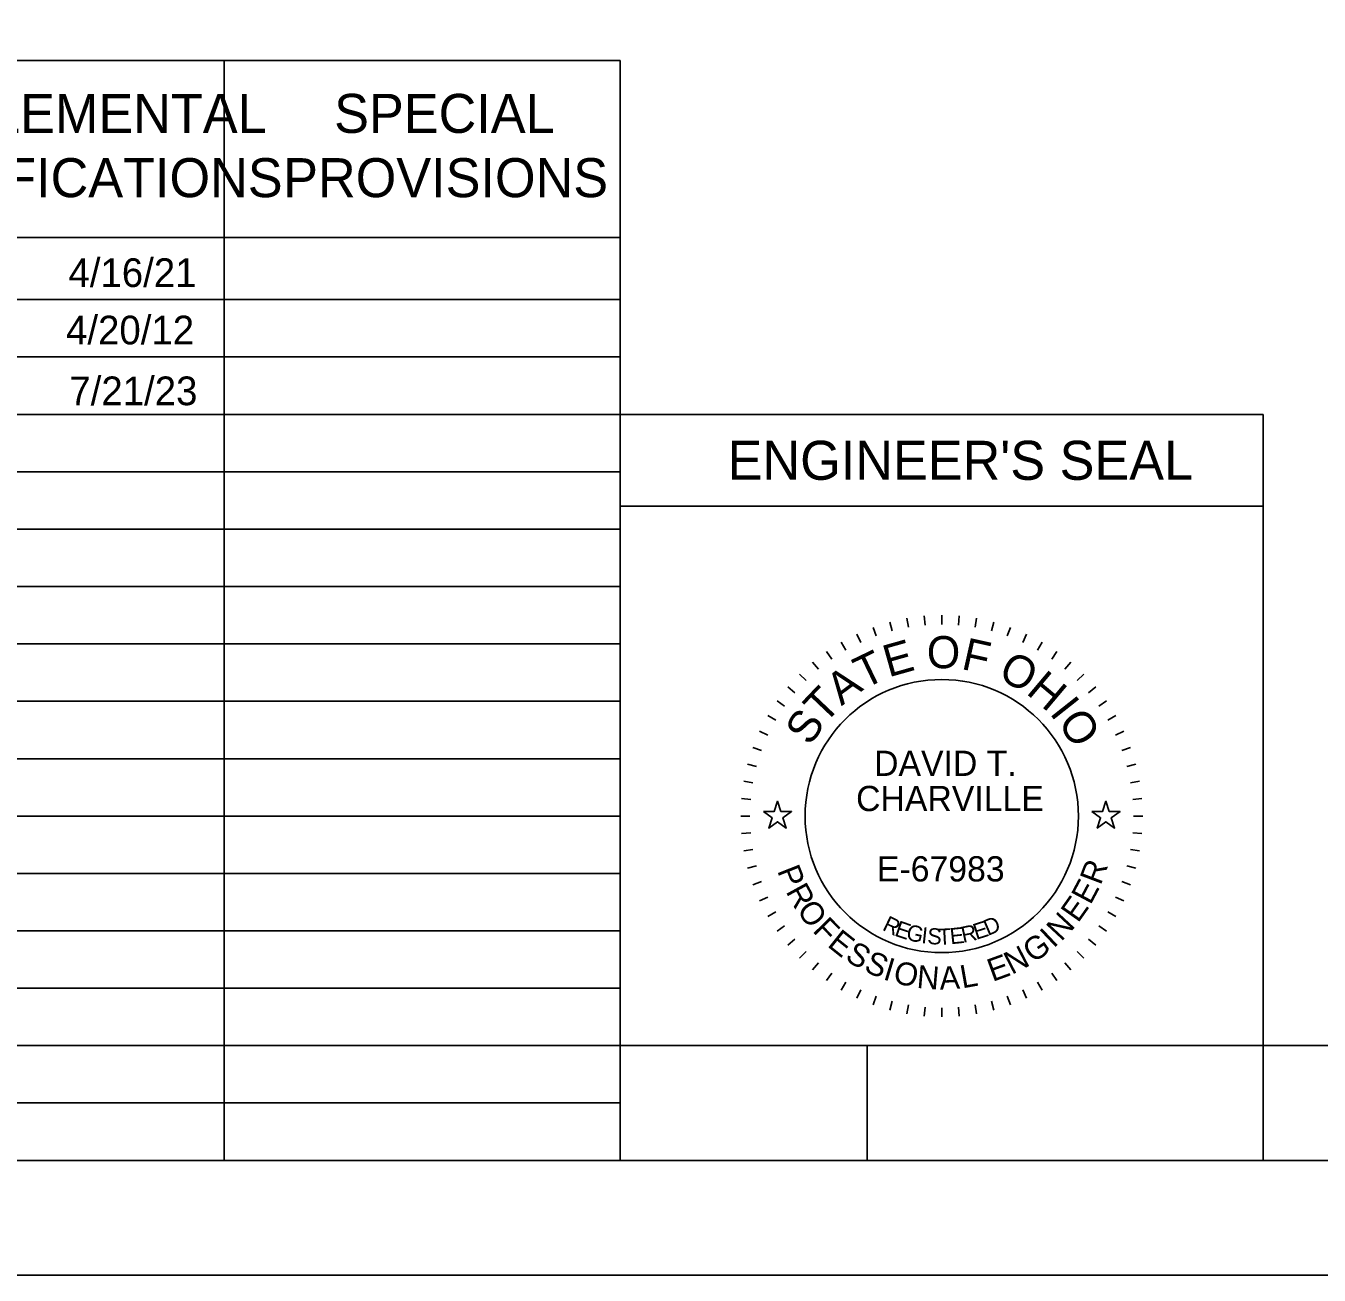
# Model space of a CAD drawing. Extents: x 0 to 40.2, y 0 to 22.
# Drawn here: x 22.74 to 28.37, y 0 to 5.44 of the extents above; entities that cross this region are included whole.
import ezdxf

# ---------------------------------------------------------------- set-up
doc = ezdxf.new("R2010")
doc.units = 0
for name, color, linetype in [('Default', 7, 'Continuous'), ('GM_X_Adjacent_County', 7, 'Continuous'), ('GM_X_Adjacent_County_Text', 7, 'Continuous'), ('GM_X_County', 7, 'Continuous'), ('GM_X_Township', 7, 'Continuous')]:
    doc.layers.add(name, color=color, linetype=linetype)

msp = doc.modelspace()

# ---------------------------------------------------------------- linework, layer by layer
at = {"layer": 'Default'}
for points in [[(25.9486, 2.02), (25.9955, 2.02), (26.01, 2.0645), (26.0245, 2.02), (26.0714, 2.02), (26.0335, 1.9924), (26.048, 1.9478), (26.01, 1.9754), (25.972, 1.9478), (25.9865, 1.9924)], [(27.3786, 2.02), (27.4255, 2.02), (27.44, 2.0645), (27.4545, 2.02), (27.5014, 2.02), (27.4635, 1.9924), (27.478, 1.9478), (27.44, 1.9754), (27.402, 1.9478), (27.4165, 1.9924)]]:
    msp.add_lwpolyline(points, close=True, dxfattribs=at)
at = {"layer": 'GM_X_Adjacent_County'}
for p, q in [((10.15, 5.2917), (23.6, 5.2917)), ((23.6, 0.5), (23.6, 5.2917)), ((23.6, 5.2917), (25.325, 5.2917)), ((25.325, 5.2917), (25.325, 0.5)), ((10.15, 4.5209), (23.6, 4.5209)), ((23.6, 4.5209), (25.325, 4.5209)), ((10.15, 4.25), (23.6, 4.25)), ((23.6, 4.25), (25.325, 4.25)), ((10.15, 4), (23.6, 4)), ((23.6, 4), (25.325, 4)), ((10.15, 3.75), (23.6, 3.75)), ((23.6, 0.5), (23.6, 3.75)), ((23.6, 3.75), (25.325, 3.75)), ((25.325, 0.5), (25.325, 3.75)), ((25.325, 3.75), (28.125, 3.75)), ((28.125, 3.75), (28.125, 0.5)), ((10.15, 3.5), (23.6, 3.5)), ((23.6, 3.5), (25.325, 3.5)), ((25.325, 3.35), (28.125, 3.35)), ((10.15, 3.25), (23.6, 3.25)), ((23.6, 3.25), (25.325, 3.25)), ((10.15, 3), (23.6, 3)), ((23.6, 3), (25.325, 3)), ((26.725, 2.875), (26.725, 2.835)), ((26.4257, 2.8222), (26.4394, 2.7846)), ((26.4985, 2.8452), (26.5089, 2.8065)), ((26.5731, 2.8617), (26.58, 2.8223)), ((26.6487, 2.8717), (26.6522, 2.8318)), ((26.8013, 2.8717), (26.7978, 2.8318)), ((26.8769, 2.8617), (26.87, 2.8223)), ((26.9515, 2.8452), (26.9411, 2.8065)), ((27.0243, 2.8222), (27.0106, 2.7846)), ((26.3552, 2.793), (26.3721, 2.7568)), ((27.0948, 2.793), (27.0779, 2.7568)), ((10.15, 2.75), (23.6, 2.75)), ((23.6, 2.75), (25.325, 2.75)), ((26.2231, 2.7168), (26.2461, 2.684)), ((26.2875, 2.7578), (26.3075, 2.7231)), ((27.1625, 2.7578), (27.1425, 2.7231)), ((27.2269, 2.7168), (27.2039, 2.684)), ((26.1626, 2.6703), (26.1883, 2.6396)), ((27.2874, 2.6703), (27.2617, 2.6396)), ((26.1063, 2.6187), (26.1346, 2.5904)), ((27.3437, 2.6187), (27.3154, 2.5904)), ((26.0547, 2.5624), (26.0854, 2.5367)), ((27.3953, 2.5624), (27.3646, 2.5367)), ((10.15, 2.5), (23.6, 2.5)), ((23.6, 2.5), (25.325, 2.5)), ((26.0082, 2.5019), (26.041, 2.4789)), ((27.4418, 2.5019), (27.409, 2.4789)), ((25.9672, 2.4375), (26.0019, 2.4175)), ((27.4828, 2.4375), (27.4481, 2.4175)), ((25.932, 2.3698), (25.9682, 2.3529)), ((27.518, 2.3698), (27.4818, 2.3529)), ((25.9028, 2.2993), (25.9404, 2.2856)), ((27.5472, 2.2993), (27.5096, 2.2856)), ((10.15, 2.25), (23.6, 2.25)), ((23.6, 2.25), (25.325, 2.25)), ((25.8798, 2.2265), (25.9185, 2.2161)), ((27.5702, 2.2265), (27.5315, 2.2161)), ((25.8633, 2.1519), (25.9027, 2.145)), ((27.5867, 2.1519), (27.5473, 2.145)), ((25.8533, 2.0763), (25.8932, 2.0728)), ((27.5967, 2.0763), (27.5568, 2.0728)), ((10.15, 2), (23.6, 2)), ((23.6, 2), (25.325, 2)), ((25.85, 2), (25.89, 2)), ((27.6, 2), (27.56, 2)), ((25.8533, 1.9237), (25.8932, 1.9272)), ((27.5967, 1.9237), (27.5568, 1.9272)), ((25.8633, 1.8481), (25.9027, 1.855)), ((27.5867, 1.8481), (27.5473, 1.855)), ((10.15, 1.75), (23.6, 1.75)), ((23.6, 1.75), (25.325, 1.75)), ((25.8798, 1.7735), (25.9185, 1.7839)), ((27.5702, 1.7735), (27.5315, 1.7839)), ((25.9028, 1.7007), (25.9404, 1.7144)), ((27.5472, 1.7007), (27.5096, 1.7144)), ((25.932, 1.6302), (25.9682, 1.6471)), ((27.518, 1.6302), (27.4818, 1.6471)), ((25.9672, 1.5625), (26.0019, 1.5825)), ((27.4828, 1.5625), (27.4481, 1.5825)), ((26.0082, 1.4981), (26.041, 1.5211)), ((27.4418, 1.4981), (27.409, 1.5211)), ((10.15, 1.5), (23.6, 1.5)), ((23.6, 1.5), (25.325, 1.5)), ((26.0547, 1.4376), (26.0854, 1.4633)), ((26.1063, 1.3813), (26.1346, 1.4096)), ((27.3437, 1.3813), (27.3154, 1.4096)), ((27.3953, 1.4376), (27.3646, 1.4633)), ((26.1626, 1.3297), (26.1883, 1.3604)), ((27.2874, 1.3297), (27.2617, 1.3604)), ((26.2231, 1.2832), (26.2461, 1.316)), ((27.2269, 1.2832), (27.2039, 1.316)), ((10.15, 1.25), (23.6, 1.25)), ((23.6, 1.25), (25.325, 1.25)), ((26.2875, 1.2422), (26.3075, 1.2769)), ((26.3552, 1.207), (26.3721, 1.2432)), ((27.0948, 1.207), (27.0779, 1.2432)), ((27.1625, 1.2422), (27.1425, 1.2769)), ((26.4257, 1.1778), (26.4394, 1.2154)), ((26.4985, 1.1548), (26.5089, 1.1935)), ((26.9515, 1.1548), (26.9411, 1.1935)), ((27.0243, 1.1778), (27.0106, 1.2154)), ((26.5731, 1.1383), (26.58, 1.1777)), ((26.6487, 1.1283), (26.6522, 1.1682)), ((26.725, 1.125), (26.725, 1.165)), ((26.8013, 1.1283), (26.7978, 1.1682)), ((26.8769, 1.1383), (26.87, 1.1777)), ((10.15, 1), (23.6, 1)), ((23.6, 1), (25.325, 1)), ((10.15, 0.75), (23.6, 0.75)), ((23.6, 0.75), (25.325, 0.75)), ((23.6, 0.5), (26.4, 0.5)), ((25.325, 0.5), (28.125, 0.5)), ((26.4, 0.5), (29.2, 0.5))]:
    msp.add_line(p, q, dxfattribs=at)
for points in [[(23.6, 0.5), (23.6, 1), (26.4, 1), (26.4, 0.5)], [(25.325, 0.5), (25.325, 1), (28.125, 1), (28.125, 0.5)], [(26.4, 0.5), (26.4, 1), (29.2, 1), (29.2, 0.5)]]:
    msp.add_lwpolyline(points, close=True, dxfattribs=at)
msp.add_circle((26.725, 2), 0.595, dxfattribs=at)
at = {"layer": 'GM_X_County'}
msp.add_lwpolyline([(0, 0), (34, 0), (34, 22), (0, 22)], close=True, dxfattribs=at)
at = {"layer": 'GM_X_Township'}
msp.add_lwpolyline([(1.5, 21.5), (33.5, 21.5), (33.5, 0.5), (1.5, 0.5)], close=True, dxfattribs=at)

# ---------------------------------------------------------------- texts
at = {"layer": 'Default'}
for s, p in [('4/16/21', (22.9222, 4.305)), ('4/20/12', (22.9117, 4.055)), ('7/21/23', (22.9261, 3.79))]:
    msp.add_text(s, height=0.125, dxfattribs=at).set_placement(p)
at = {"layer": 'GM_X_Adjacent_County'}
for s, height, p in [("ENGINEER'S SEAL", 0.17, (25.7926, 3.465)), ('DAVID T.', 0.11, (26.4304, 2.1749)), ('CHARVILLE', 0.11, (26.3521, 2.0216)), ('E-67983', 0.11, (26.4427, 1.7151))]:
    msp.add_text(s, height=height, dxfattribs=at).set_placement(p)
for s, height, rotation, p in [('E', 0.14, 15.7571, (26.4934, 2.6038)), ('O', 0.14, 359.7812, (26.6597, 2.6443)), ('F', 0.14, 347.4362, (26.8061, 2.6417)), ('T', 0.14, 25.7167, (26.3866, 2.5518)), ('O', 0.14, 332.2586, (26.9648, 2.6015)), ('A', 0.14, 36.4747, (26.2884, 2.4781)), ('H', 0.14, 319.9136, (27.0882, 2.5361)), ('T', 0.14, 46.4344, (26.2133, 2.3964)), ('I', 0.14, 308.367, (27.1915, 2.4483)), ('S', 0.14, 57.1924, (26.1531, 2.3014)), ('O', 0.14, 303.1491, (27.2271, 2.4089)), ('R', 0.1, 69.2322, (27.4169, 1.6954)), ('P', 0.1, 291.494, (26.0073, 1.7621)), ('R', 0.1, 298.7311, (26.044, 1.6717)), ('E', 0.1, 61.9951, (27.3726, 1.6098)), ('E', 0.1, 54.758, (27.3183, 1.5314)), ('O', 0.1, 306.4666, (26.0905, 1.5883)), ('N', 0.1, 47.0224, (27.2452, 1.4508)), ('F', 0.1, 314.7068, (26.1593, 1.4983)), ('R', 0.07, 334.487, (26.4625, 1.5051)), ('E', 0.07, 341.04, (26.5156, 1.4801)), ('G', 0.07, 347.4752, (26.5664, 1.4618)), ('R', 0.07, 11.9184, (26.8175, 1.4474)), ('E', 0.07, 17.6836, (26.8748, 1.4602)), ('D', 0.07, 23.3052, (26.926, 1.477)), ('E', 0.1, 321.4393, (26.2228, 1.4348)), ('I', 0.07, 353.7858, (26.6341, 1.4468)), ('S', 0.07, 356.8926, (26.6608, 1.4429)), ('T', 0.07, 3.0061, (26.7107, 1.4387)), ('E', 0.07, 6.0117, (26.7639, 1.4412)), ('G', 0.1, 35.0469, (27.1231, 1.357)), ('I', 0.1, 43.287, (27.2118, 1.4214)), ('S', 0.1, 328.6764, (26.2993, 1.3752)), ('N', 0.1, 27.3113, (27.0295, 1.3075)), ('S', 0.1, 335.9134, (26.3814, 1.3266)), ('I', 0.1, 343.1505, (26.4656, 1.2897)), ('O', 0.1, 346.8859, (26.5089, 1.2751)), ('L', 0.1, 10.0987, (26.8144, 1.249)), ('E', 0.1, 20.0742, (26.9462, 1.277)), ('N', 0.1, 355.1261, (26.6138, 1.2517)), ('A', 0.1, 2.8617, (26.7173, 1.2437))]:
    msp.add_text(s, height=height, rotation=rotation, dxfattribs=at).set_placement(p)
at = {"layer": 'GM_X_Adjacent_County_Text'}
for s, p in [('SUPPLEMENTAL', (21.9661, 4.9763)), ('SPECIAL', (24.0792, 4.9763)), ('SPECIFICATIONS', (21.9602, 4.6963)), ('PROVISIONS', (23.8573, 4.6963))]:
    msp.add_text(s, height=0.17, dxfattribs=at).set_placement(p)

doc.saveas('drawing.dxf')
